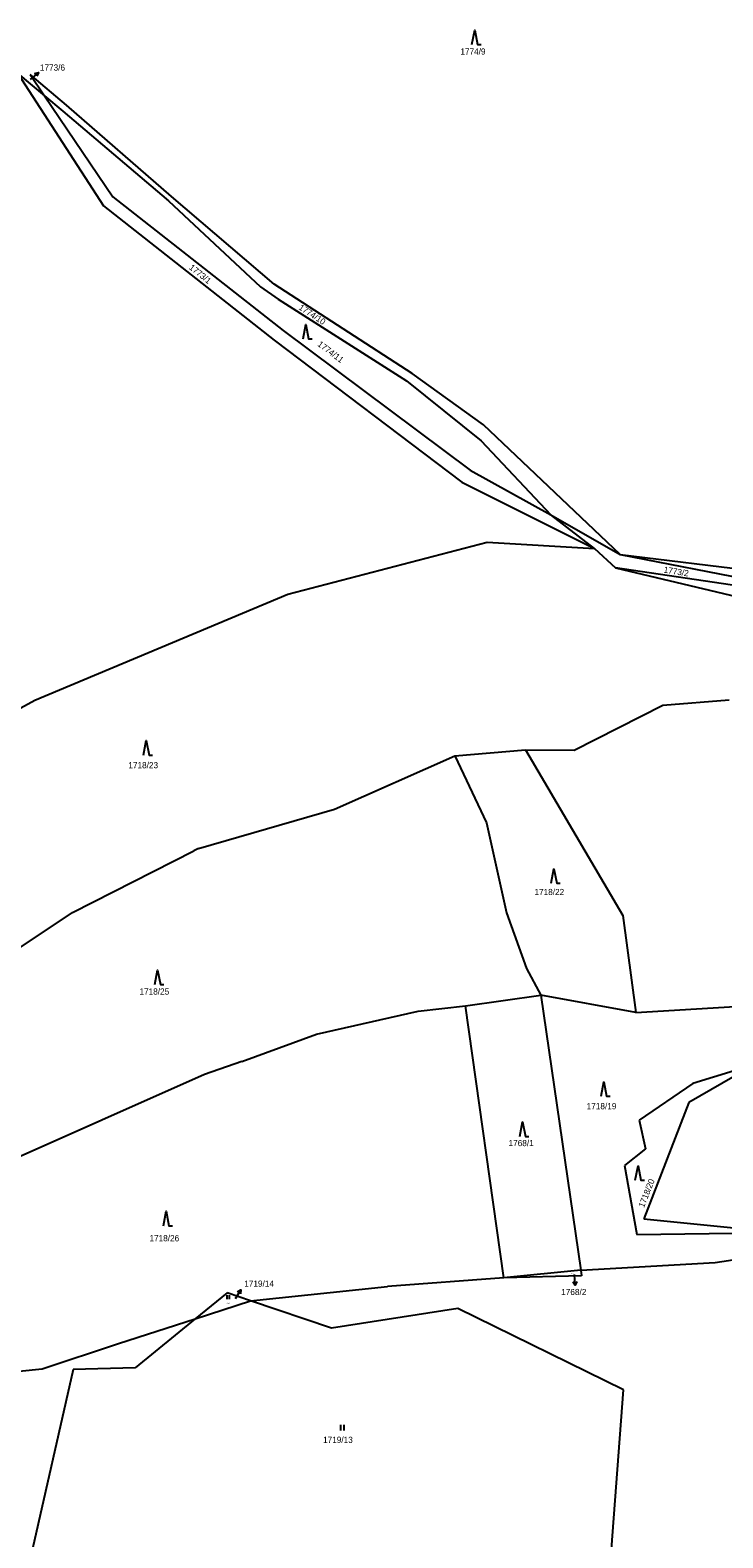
# Model space of a CAD drawing. Extents: x -609861 to -605046, y -1120287 to -1116307.
# Drawn here: x -608923.4 to -608732, y -1118858.4 to -1118442.1 of the extents above; entities that cross this region are included whole.
import ezdxf

# ---------------------------------------------------------------- set-up
doc = ezdxf.new("R2010")
doc.units = 0
for name, color, linetype in [('Vrstva 1', 7, 'Continuous'), ('Vrstva 2', 7, 'Continuous'), ('Vrstva 3', 7, 'Continuous'), ('Vrstva 7', 7, 'Continuous')]:
    doc.layers.add(name, color=color, linetype=linetype)

msp = doc.modelspace()

# ---------------------------------------------------------------- linework, layer by layer
at = {"layer": 'Vrstva 1'}
for p, q in [((-608926.73, -1118454.06), (-608919.38, -1118460.24)), ((-608926.73, -1118454.06), (-608903.09, -1118490.59)), ((-608913.29, -1118462.74), (-608923.38, -1118454.33)), ((-608923.38, -1118454.33), (-608919.38, -1118460.24)), ((-608919.38, -1118460.24), (-608914.37, -1118464.46)), ((-608919.38, -1118460.24), (-608900.53, -1118488.1)), ((-608914.37, -1118464.46), (-608885.16, -1118489.23)), ((-608884.31, -1118487.97), (-608913.29, -1118462.74)), ((-608903.09, -1118490.59), (-608855.91, -1118527.65)), ((-608900.53, -1118488.1), (-608853.45, -1118524.96)), ((-608885.16, -1118489.23), (-608859.75, -1118512.98)), ((-608855.98, -1118512.2), (-608884.31, -1118487.97)), ((-608859.75, -1118512.98), (-608854.86, -1118516.37)), ((-608817.78, -1118536.84), (-608855.98, -1118512.2)), ((-608854.86, -1118516.37), (-608819.43, -1118538.9)), ((-608855.91, -1118527.65), (-608804.12, -1118566.91)), ((-608853.45, -1118524.96), (-608801.84, -1118563.61)), ((-608819.43, -1118538.9), (-608798.74, -1118555.46)), ((-608798.09, -1118551.08), (-608817.78, -1118536.84)), ((-608760.35, -1118586.83), (-608798.09, -1118551.08)), ((-608798.74, -1118555.46), (-608779.49, -1118575.94)), ((-608801.84, -1118563.61), (-608779.49, -1118575.94)), ((-608804.12, -1118566.91), (-608767.49, -1118585.16)), ((-608767.49, -1118585.16), (-608779.49, -1118575.94)), ((-608779.49, -1118575.94), (-608760.35, -1118586.83)), ((-608852.18, -1118597.77), (-608797.06, -1118583.49)), ((-608797.06, -1118583.49), (-608767.49, -1118585.16)), ((-608767.49, -1118585.16), (-608761.65, -1118590.57)), ((-608711.36, -1118597.94), (-608761.65, -1118590.57)), ((-608761.65, -1118590.57), (-608720.83, -1118600.2)), ((-608760.35, -1118586.83), (-608721.92, -1118591.49)), ((-608760.35, -1118586.83), (-608719.44, -1118594.85)), ((-608884.05, -1118611.12), (-608852.18, -1118597.77)), ((-608922.04, -1118627.03), (-608884.05, -1118611.12)), ((-608943.83, -1118638.8), (-608922.04, -1118627.03)), ((-608748.53, -1118628.45), (-608730.24, -1118626.98)), ((-608773.11, -1118640.91), (-608748.53, -1118628.45)), ((-608839.3, -1118657.14), (-608806.06, -1118642.41)), ((-608806.06, -1118642.41), (-608786.47, -1118640.83)), ((-608806.06, -1118642.41), (-608797.33, -1118660.93)), ((-608786.47, -1118640.83), (-608759.64, -1118686.56)), ((-608786.47, -1118640.83), (-608773.11, -1118640.91)), ((-608876.88, -1118668.03), (-608839.3, -1118657.14)), ((-608797.33, -1118660.93), (-608791.8, -1118685.77)), ((-608911.65, -1118685.74), (-608878.17, -1118668.65)), ((-608876.88, -1118668.03), (-608878.17, -1118668.65)), ((-608947.28, -1118709.38), (-608911.65, -1118685.74)), ((-608791.8, -1118685.77), (-608786.26, -1118701.14)), ((-608759.64, -1118686.56), (-608756.02, -1118713.36)), ((-608786.26, -1118701.14), (-608782.3, -1118708.5)), ((-608803.05, -1118711.46), (-608782.3, -1118708.5)), ((-608756.02, -1118713.36), (-608782.3, -1118708.5)), ((-608782.3, -1118708.5), (-608771.22, -1118784.46)), ((-608756.02, -1118713.36), (-608717.26, -1118711)), ((-608844.24, -1118719.33), (-608816.12, -1118712.97)), ((-608816.12, -1118712.97), (-608803.05, -1118711.46)), ((-608792.54, -1118786.58), (-608803.05, -1118711.46)), ((-608864.86, -1118726.86), (-608844.24, -1118719.33)), ((-608864.86, -1118726.86), (-608875.16, -1118730.44)), ((-608723.11, -1118727.69), (-608741.39, -1118738.19)), ((-608723.11, -1118727.69), (-608740.31, -1118732.9)), ((-608875.16, -1118730.44), (-608932.03, -1118755.68)), ((-608740.31, -1118732.9), (-608755.12, -1118743.03)), ((-608741.39, -1118738.19), (-608753.79, -1118770.33)), ((-608755.12, -1118743.03), (-608753.4, -1118750.98)), ((-608753.4, -1118750.98), (-608759.2, -1118755.55)), ((-608759.2, -1118755.55), (-608755.76, -1118774.62)), ((-608753.79, -1118770.33), (-608716.42, -1118774.06)), ((-608755.76, -1118774.62), (-608716.42, -1118774.06)), ((-608734.12, -1118782.36), (-608702.45, -1118777.63)), ((-608771.22, -1118784.46), (-608792.54, -1118786.58)), ((-608771, -1118786), (-608792.54, -1118786.58)), ((-608771.22, -1118784.46), (-608734.12, -1118782.36)), ((-608771.22, -1118784.46), (-608771, -1118786)), ((-608862.46, -1118792.91), (-608824.62, -1118788.94)), ((-608792.54, -1118786.58), (-608824.62, -1118788.94)), ((-608868.96, -1118790.7), (-608877.76, -1118797.87)), ((-608877.76, -1118797.87), (-608862.46, -1118792.91)), ((-608862.46, -1118792.91), (-608868.96, -1118790.7)), ((-608840.1, -1118800.52), (-608862.46, -1118792.91)), ((-608898.97, -1118804.75), (-608877.76, -1118797.87)), ((-608877.76, -1118797.87), (-608894.37, -1118811.41)), ((-608805.21, -1118795.01), (-608840.1, -1118800.52)), ((-608759.42, -1118817.54), (-608805.21, -1118795.01)), ((-608920, -1118811.71), (-608898.97, -1118804.75)), ((-608958.64, -1118815.48), (-608920, -1118811.71)), ((-608911.44, -1118811.9), (-608923.15, -1118863.4)), ((-608894.37, -1118811.41), (-608911.44, -1118811.9)), ((-608762.79, -1118861.5), (-608759.42, -1118817.54))]:
    msp.add_line(p, q, dxfattribs=at)
at = {"layer": 'Vrstva 3'}
for p, q in [((-608869, -1118791.41), (-608869, -1118792.46)), ((-608868.3, -1118792.46), (-608868.3, -1118791.41)), ((-608837.64, -1118827.2), (-608837.64, -1118828.7)), ((-608836.64, -1118828.7), (-608836.64, -1118827.2))]:
    msp.add_line(p, q, dxfattribs=at)
for points in [[(-608801.3, -1118446.07), (-608800.55, -1118442.07), (-608799.8, -1118446.07), (-608798.8, -1118446.07)], [(-608847.95, -1118527.32), (-608847.2, -1118523.32), (-608846.45, -1118527.32), (-608845.45, -1118527.32)], [(-608892.02, -1118642.23), (-608891.27, -1118638.23), (-608890.52, -1118642.23), (-608889.52, -1118642.23)], [(-608779.4, -1118677.64), (-608778.65, -1118673.64), (-608777.9, -1118677.64), (-608776.9, -1118677.64)], [(-608888.88, -1118705.61), (-608888.13, -1118701.61), (-608887.38, -1118705.61), (-608886.38, -1118705.61)], [(-608765.61, -1118736.44), (-608764.86, -1118732.44), (-608764.11, -1118736.44), (-608763.11, -1118736.44)], [(-608788.05, -1118747.52), (-608787.3, -1118743.52), (-608786.55, -1118747.52), (-608785.55, -1118747.52)], [(-608756.18, -1118759.61), (-608755.43, -1118755.61), (-608754.68, -1118759.61), (-608753.68, -1118759.61)], [(-608886.5, -1118772.21), (-608885.75, -1118768.21), (-608885, -1118772.21), (-608884, -1118772.21)]]:
    msp.add_lwpolyline(points, dxfattribs=at)
at = {"layer": 'Vrstva 7'}
for p, q in [((-608921.062, -1118453.728), (-608923.34, -1118455.68)), ((-608772.781, -1118788.635), (-608772.95, -1118785.64)), ((-608865.131, -1118789.872), (-608866.73, -1118792.41))]:
    msp.add_line(p, q, dxfattribs=at)
for points in [[(-608922.147, -1118453.999), (-608921.062, -1118453.728), (-608921.496, -1118454.758)], [(-608866.087, -1118790.451), (-608865.131, -1118789.872), (-608865.241, -1118790.984)], [(-608772.338, -1118787.609), (-608772.781, -1118788.635), (-608773.336, -1118787.665)]]:
    msp.add_lwpolyline(points, dxfattribs=at)

# ---------------------------------------------------------------- texts
at = {"layer": 'Vrstva 2'}
for s, height, p in [('1774/9', 1.7, (-608804.497, -1118448.81)), ('1718/23', 1.7, (-608896.227, -1118645.87)), ('1718/22', 1.7, (-608784.037, -1118680.89)), ('1718/25', 1.7, (-608893.157, -1118708.37)), ('1718/19', 1.7, (-608769.617, -1118740.03)), ('1768/1', 1.7, (-608791.197, -1118750.22)), ('1718/26', 1.7, (-608890.397, -1118776.49)), ('1768/2', 0.2, (-608774.054, -1118785.43)), ('1719/14', 0.2, (-608869.064, -1118793.68)), ('1719/13', 1.7, (-608842.437, -1118832.15))]:
    msp.add_text(s, height=height, dxfattribs=at).set_placement(p)
for s, rotation, p in [('1773/1', 321.31473, (-608879.613, -1118507.875)), ('1774/10', 326.70054, (-608849.332, -1118519.026)), ('1774/11', 323.0909, (-608844.126, -1118529.116)), ('1773/2', 350.99394, (-608748.432, -1118591.841)), ('1718/20', 68.41116, (-608753.786, -1118767.325))]:
    msp.add_text(s, height=1.7, rotation=rotation, dxfattribs=at).set_placement(p)
at = {"layer": 'Vrstva 7'}
for s, p in [('1773/6', (-608920.677, -1118453.25)), ('1719/14', (-608864.207, -1118789.03)), ('1768/2', (-608776.655, -1118791.34))]:
    msp.add_text(s, height=1.7, dxfattribs=at).set_placement(p)

doc.saveas('drawing.dxf')
